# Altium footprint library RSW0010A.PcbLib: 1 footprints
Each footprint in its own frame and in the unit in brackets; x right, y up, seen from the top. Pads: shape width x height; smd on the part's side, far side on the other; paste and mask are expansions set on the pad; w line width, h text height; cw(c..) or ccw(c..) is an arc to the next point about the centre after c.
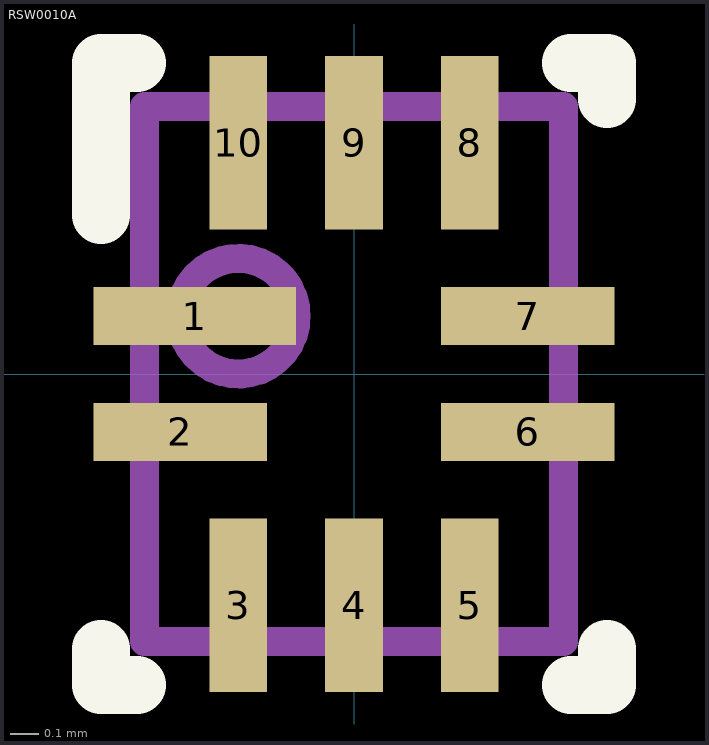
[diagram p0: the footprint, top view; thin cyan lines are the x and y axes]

## RSW0010A [mm] "QFN, 10-Leads, Body 1.8x1.4 mm, Pitch 0.4mm, TI Recommended"
height 0.55
pads (10):
  rect 0.7x0.2 smd: 1(-0.55,0.2)
  rect 0.6x0.2 smd: 2(-0.6,-0.2) 6(0.6,-0.2) 7(0.6,0.2)
  rect 0.2x0.6 smd: 3(-0.4,-0.8) 4(0,-0.8) 5(0.4,-0.8) 8(0.4,0.8) 9(0,0.8) 10(-0.4,0.8)
Top Overlay:
  lines w0.2: -0.875,-0.95 -0.875,-1.075 -0.75,-1.075 ; -0.875,0.55 -0.875,1.075 -0.75,1.075 ; 0.75,-1.075 0.875,-1.075 0.875,-0.95 ; 0.75,1.075 0.875,1.075 0.875,0.95
M5 Assembly Top:
  circle w0.1: c-0.4,0.2 r0.2
  lines w0.1: -0.725,-0.925 0.725,-0.925 0.725,0.925 -0.725,0.925 -0.725,-0.925
  text ".Designator" at 0.125,0.725 h0.38
3D body: height 0.56, standoff 0.5, extent -0.603,-0.003 -0.197,0.403
3D body: height 0.55, standoff 0, extent -0.725,-0.925 0.725,0.925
